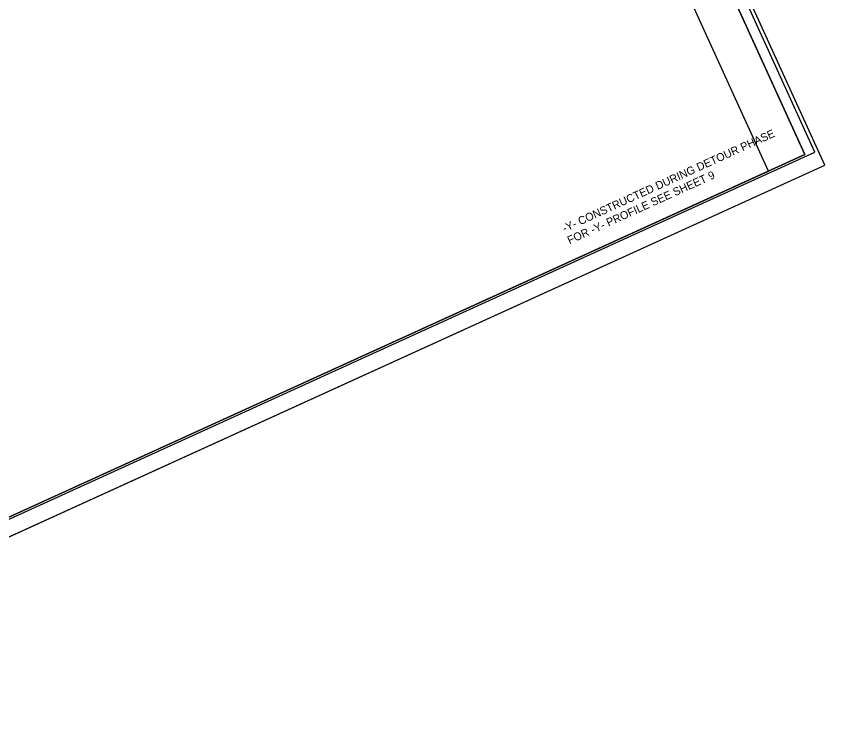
# Model space of a CAD drawing. Extents: x 2249019 to 2251039, y 663030 to 664799.
# Drawn here: x 2250029 to 2251039, y 663030 to 663915 of the extents above; entities that cross this region are included whole.
import ezdxf

# ---------------------------------------------------------------- set-up
doc = ezdxf.new("R2010")
doc.units = 0
for name, color, linetype in [('Prop Dimension', 7, 'Continuous'), ('Sheet Clip Boundary CELL', 7, 'Continuous'), ('Sheet Cutting Line CELL', 7, 'Continuous'), ('Sheet Layout Plan Border', 7, 'Continuous'), ('Sheet Plan CELL', 7, 'Continuous'), ('Sheet Plan Layout CELL', 7, 'Continuous'), ('Sheet Plot Border Inside CELL', 7, 'Continuous'), ('Sheet Plot Border Outside CELL', 7, 'Continuous')]:
    doc.layers.add(name, color=color, linetype=linetype)

msp = doc.modelspace()

# ---------------------------------------------------------------- linework, layer by layer
at = {"layer": 'Sheet Clip Boundary CELL'}
msp.add_lwpolyline([(2249425.3, 663908.7), (2249673.4, 663362.4), (2249790, 663300.9), (2249798.4, 663191.7), (2249694.8, 663140.6), (2250968.8, 663721.1), (2250621.1, 664484.2), (2250448.8, 664405.7), (2250361.1, 664598.1), (2249259.4, 664096.1)], close=True, dxfattribs=at)
at = {"layer": 'Sheet Cutting Line CELL'}
msp.add_line((2249507.1, 663030.3), (2251039.1, 663728.4), dxfattribs=at)
at = {"layer": 'Sheet Layout Plan Border'}
msp.add_lwpolyline([(2249694.8, 663140.6), (2250968.8, 663721.1), (2250621.1, 664484.2), (2250448.8, 664405.7), (2250361.1, 664598.1), (2249259.4, 664096.1)], close=True, dxfattribs=at)
at = {"layer": 'Sheet Plan CELL'}
for points in [[(2250578.9, 664697.4), (2249213.9, 664075.3), (2249649.3, 663119.9), (2251014.2, 663741.9)], [(2249649.3, 663119.9), (2249213.9, 664075.3), (2250396.8, 664614.4), (2250459, 664477.9), (2250641.1, 664560.8), (2251014.2, 663741.9)]]:
    msp.add_lwpolyline(points, close=True, dxfattribs=at)
at = {"layer": 'Sheet Plan Layout CELL'}
msp.add_lwpolyline([(2249213.9, 664075.3), (2249649.3, 663119.9), (2251014.2, 663741.9), (2250666.5, 664504.9), (2250448.8, 664405.7), (2250361.1, 664598.1)], close=True, dxfattribs=at)
at = {"layer": 'Sheet Plot Border Inside CELL'}
msp.add_lwpolyline([(2249510.6, 663053.9), (2251026.6, 663744.8), (2250589.2, 664704.8), (2249073.2, 664014)], close=True, dxfattribs=at)
at = {"layer": 'Sheet Plot Border Outside CELL'}
msp.add_lwpolyline([(2249507.1, 663030.3), (2251039.1, 663728.4), (2250585, 664724.9), (2249053.1, 664026.8)], close=True, dxfattribs=at)

# ---------------------------------------------------------------- texts
at = {"layer": 'Prop Dimension'}
for s, p in [('-Y- CONSTRUCTED DURING DETOUR PHASE', (2250714, 663644.4)), ('FOR -Y- PROFILE SEE SHEET 9', (2250720.2, 663629.5))]:
    msp.add_text(s, height=10, rotation=24.4979, dxfattribs=at).set_placement(p)

doc.saveas('drawing.dxf')
